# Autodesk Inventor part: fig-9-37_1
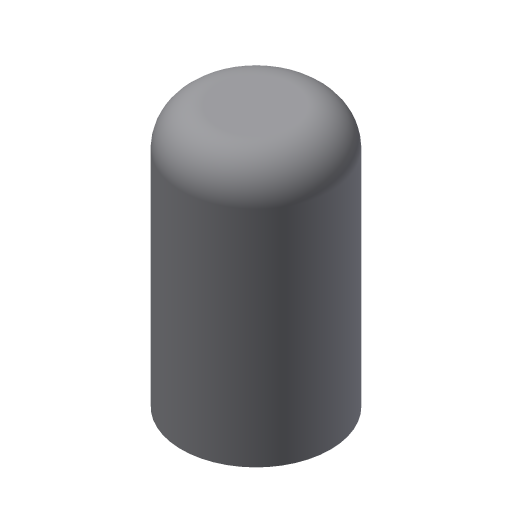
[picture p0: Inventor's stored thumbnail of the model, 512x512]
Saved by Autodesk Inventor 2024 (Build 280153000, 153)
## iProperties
Created: 2013-03
Part Number: fig-9-37_1
Material: Generic
Document SubType Name: Modeling
Designer: CADCIM
Density: 1 g/cm^3
Appearance: Default
Author: CADCIM
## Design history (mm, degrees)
sketch "Sketch1"
  geometry: C1 r 10 at (0, 0); 1 further point
  constraints: 1 centre point, 1 coincident
  dimensions: "d0" = 20 diameter of C1
extrude "Extrusion1" new body sketch "Sketch1" distance "d2" = 35; taper "d3" = 0 deg
fillet "Fillet1" dims "d4" = 5
shell "Shell1" dims "d5" = 2
body "Solid1"
